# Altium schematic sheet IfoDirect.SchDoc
size A; DocumentNumber: 3; SheetNumber: 3; SheetTotal: 8; pInstance: Corner
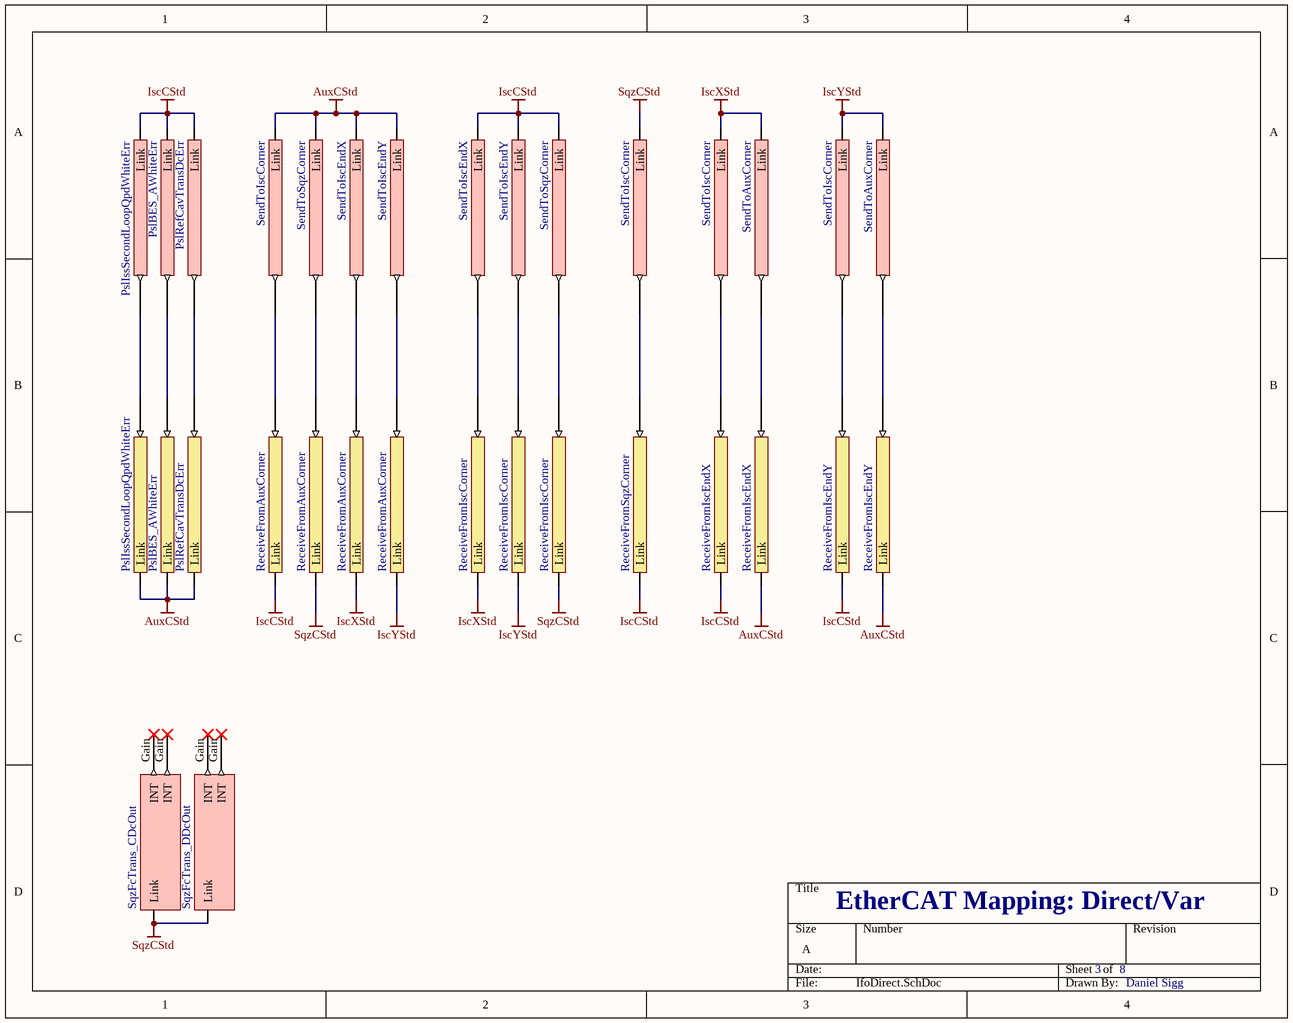
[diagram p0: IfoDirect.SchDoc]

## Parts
V1  PslIssSecondLoopQpdWhiteErr  (no BOM)
V2  PslBES_AWhiteErr  (no BOM)
V3  PslRefCavTransDcErr  (no BOM)
V4  SendToIscCorner  (no BOM)
V5  SendToSqzCorner  (no BOM)
V6  SendToIscEndX  (no BOM)
V7  SendToIscEndY  (no BOM)
V8  SendToIscEndX  (no BOM)
V9  SendToIscEndY  (no BOM)
V10  SendToSqzCorner  (no BOM)
V11  SendToAuxCorner  (no BOM)
V12  SendToAuxCorner  (no BOM)
V13  SendToIscCorner  (no BOM)
V14  SendToIscCorner  (no BOM)
V15  SendToIscCorner  (no BOM)
V16  PslIssSecondLoopQpdWhiteErr  (no BOM)
V17  PslBES_AWhiteErr  (no BOM)
V18  PslRefCavTransDcErr  (no BOM)
V19  ReceiveFromAuxCorner  (no BOM)
V20  ReceiveFromAuxCorner  (no BOM)
V21  ReceiveFromAuxCorner  (no BOM)
V22  ReceiveFromAuxCorner  (no BOM)
V23  ReceiveFromIscCorner  (no BOM)
V24  ReceiveFromIscCorner  (no BOM)
V26  ReceiveFromIscCorner  (no BOM)
V27  ReceiveFromIscEndX  (no BOM)
V28  ReceiveFromIscEndY  (no BOM)
V29  ReceiveFromSqzCorner  (no BOM)
V30  ReceiveFromIscEndX  (no BOM)
V31  ReceiveFromIscEndY  (no BOM)
V840  SqzFcTrans_DDcOut  (no BOM)
V841  SqzFcTrans_CDcOut  (no BOM)

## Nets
AuxCStd: V4.?2(Link) V5.?2(Link) V6.?2(Link) V7.?2(Link) V16.?2(Link) V17.?2(Link) V18.?2(Link) V27.?2(Link) V28.?2(Link)
IscCStd: V1.?2(Link) V2.?2(Link) V3.?2(Link) V8.?2(Link) V9.?2(Link) V10.?2(Link) V19.?2(Link) V29.?2(Link) V30.?2(Link) V31.?2(Link)
IscXStd: V11.?2(Link) V14.?2(Link) V21.?2(Link) V23.?2(Link)
IscYStd: V12.?2(Link) V15.?2(Link) V22.?2(Link) V24.?2(Link)
SqzCStd: V13.?2(Link) V20.?2(Link) V26.?2(Link) V840.0(Link) V841.0(Link)
NetV1_?1: V1.?1 V16.?1
NetV2_?1: V2.?1 V17.?1
NetV3_?1: V3.?1 V18.?1
NetV4_?1: V4.?1 V19.?1
NetV5_?1: V5.?1 V20.?1
NetV6_?1: V6.?1 V21.?1
NetV7_?1: V7.?1 V22.?1
NetV8_?1: V8.?1 V23.?1
NetV9_?1: V9.?1 V24.?1
NetV10_?1: V10.?1 V26.?1
NetV11_?1: V11.?1 V27.?1
NetV12_?1: V12.?1 V28.?1
NetV13_?1: V13.?1 V29.?1
NetV14_?1: V14.?1 V30.?1
NetV15_?1: V15.?1 V31.?1

Not connected (* = marked no-connect by the designer): V840 Gain(INT)*; V841 Gain(INT)*

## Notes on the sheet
- EtherCAT Mapping: Direct/Var
- Daniel Sigg

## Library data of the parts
V1-V3 = VariableOutBOOL: BOOL; Instance: H1IscCorner Instance; PLC: H1IscCorner; Task: IscCStd
V4 = VariableOut: CornerPLC1toCornerPLC2Struct; Instance: H1AuxCorner Instance; PLC: H1AuxCorner; Task: AuxCStd
V5 = VariableOut: CornerPLC1toCornerPLC4Struct; Instance: H1AuxCorner Instance; PLC: H1AuxCorner; Task: AuxCStd
V6 V7 = VariableOut: CornerPLC1toEndStruct; Instance: H1AuxCorner Instance; PLC: H1AuxCorner; Task: AuxCStd
V8 V9 = VariableOut: CornerPLC2toEndStruct; Instance: H1IscCorner Instance; PLC: H1IscCorner; Task: IscCStd
V10 = VariableOut: CornerPLC2toCornerPLC4Struct; Instance: H1IscCorner Instance; PLC: H1IscCorner; Task: IscCStd
V11 V14 = VariableOut: EndtoCornerPLC2Struct; Instance: H1IscEndX Instance; PLC: H1IscEndX; Task: IscEStd
V12 V15 = VariableOut: EndtoCornerPLC2Struct; Instance: H1IscEndY Instance; PLC: H1IscEndY; Task: IscEStd
V13 = VariableOut: CornerPLC4toCornerPLC2Struct; Instance: H1SqzCorner Instance; PLC: H1SqzCorner; Task: SqzCStd
V16-V18 = VariableInBOOL: BOOL; Instance: H1AuxCorner Instance; PLC: H1AuxCorner; Task: AuxCStd
V19 = VariableIn: CornerPLC1toCornerPLC2Struct; Instance: H1IscCorner Instance; PLC: H1IscCorner; Task: IscCStd
V20 = VariableIn: CornerPLC1toCornerPLC4Struct; Instance: H1SqzCorner Instance; PLC: H1SqzCorner; Task: SqzCStd
V21 = VariableIn: CornerPLC1toEndStruct; Instance: H1IscEndX Instance; PLC: H1IscEndX; Task: IscEStd
V22 = VariableIn: CornerPLC1toEndStruct; Instance: H1IscEndY Instance; PLC: H1IscEndY; Task: IscEStd
V23 = VariableIn: CornerPLC2toEndStruct; Instance: H1IscEndX Instance; PLC: H1IscEndX; Task: IscEStd
V24 = VariableIn: CornerPLC2toEndStruct; Instance: H1IscEndY Instance; PLC: H1IscEndY; Task: IscEStd
V26 = VariableIn: CornerPLC2toCornerPLC4Struct; Instance: H1SqzCorner Instance; PLC: H1SqzCorner; Task: SqzCStd
V27 V28 = VariableIn: EndtoCornerPLC2Struct; Instance: H1AuxCorner Instance; PLC: H1AuxCorner; Task: AuxCStd
V29 = VariableIn: CornerPLC4toCornerPLC2Struct; Instance: H1IscCorner Instance; PLC: H1IscCorner; Task: IscCStd
V30 V31 = VariableIn: EndtoCornerPLC2Struct; Instance: H1IscCorner Instance; PLC: H1IscCorner; Task: IscCStd
V840 V841 = DCPower_DCPowerOutStruct: DCPowerOutStruct; BoxType: Variable; Instance: H1SqzCorner Instance; PLC: H1SqzCorner; Task: SqzCStd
